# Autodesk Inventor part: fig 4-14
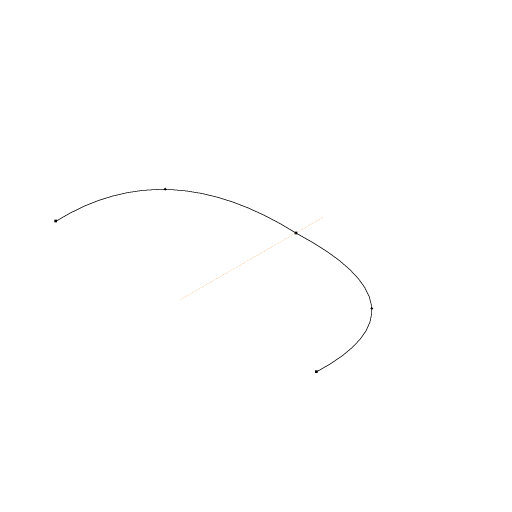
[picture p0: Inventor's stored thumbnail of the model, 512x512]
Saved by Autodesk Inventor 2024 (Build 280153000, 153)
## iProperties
Created: 2012-07
Part Number: fig 4-14
Material: Generic
Document SubType Name: Modeling
Designer: CADCIM
Density: 1 g/cm^3
Appearance: Default
Author: CADCIM
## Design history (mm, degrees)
sketch "Sketch1"
  geometry: L1 (-0.121, 16.232)-(-0.121, 0.498); 5 further points
  constraints: 2 end point, 2 symmetric about line, 1 vertical, 7 other
